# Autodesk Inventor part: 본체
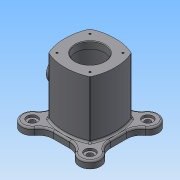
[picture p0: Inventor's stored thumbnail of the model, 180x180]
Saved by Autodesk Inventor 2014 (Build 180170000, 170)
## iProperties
Created: 2016-05
Part Number: 본체
Material: 일반
Document SubType Name: Modeling
Designer: NET
Density: 1 g/cm^3
Appearance: 기본값
Author: NET
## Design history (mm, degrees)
sketch "스케치5"
  geometry: L1 (0, 43)-(0, -43); L2 (-43, 0)-(43, 0); L3 (0, 0)-(35.355, 35.355); L4 (0, 0)-(-35.355, 35.355); L5 (0, 0)-(-35.355, -35.355); L6 (0, 0)-(35.355, -35.355); 4 further points; 4 other entities
  constraints: 12 end point, 2 coincident, 2 horizontal, 2 horizontal alignment, 2 midpoint, 2 vertical alignment, 18 other
  dimensions: "d44" = 50 distance of L3.end L3.start; "d46" = 50 distance of L4.end L3.start; "d47" = 50 distance of L5.end L3.start; "d48" = 45 deg angle of L2 L3; "d49" = 45 deg angle of L1 L4; "d50" = 45 deg angle of L1 L5; "d51" = 50 distance of L6.end L3.start; "d52" = 45 deg angle of L2 L6; "d53" = 86 distance of L1.end L1.start; "d54" = 86 distance of L2.start L2.end
extrude "돌출3" new body sketch "스케치5" distance "d55" = 110; taper "d56" = 0 deg
fillet "모깎기3" dims "d57" = 3
sketch "스케치6"
  geometry: L1 (110, -34.353)-(110, 34.353) reference; L2 (0, -34.353)-(0, 34.353) reference; L3 (110, 0)-(0, 0); L4 (110, -25)-(98, -25); L5 (98, -25)-(98, 0); L6 (98, -35)-(12, -35); L7 (12, -35)-(12, 0); L8 (0, -25)-(12, -25); L9 (12, -25)-(12, 0); L10 (98, -35)-(98, -25)
  constraints: 16 end point, 6 perpendicular, 5 point on line, 2 parallel, 1 midpoint
  dimensions: "d58" = 70 diameter of L6 L3; "d59" = 50 diameter of L4 L3; "d60" = 50 diameter of L8 L3; "d61" = 12 distance between parallel lines of L1 L5; "d62" = 12 distance between parallel lines of L2 L7
revolve "회전1" sketch "스케치6" stored, may be unused: angle "d63" = 90 deg
sketch "스케치7"
  geometry: L1 (-49, 49)-(49, 49); L2 (49, 49)-(49, -49); L3 (49, -49)-(-49, -49); L4 (-49, -49)-(-49, 49); L5 (0, 0)-(-49.497, -49.497); L6 (0, 0)-(0, -70); A1 r 18 centre (-49.497, -49.497) between (-34.706, -59.754) and (-59.754, -34.706); A2 r 25 centre (-14.162, -74) between (-14.162, -49) and (-34.706, -59.754); A3 r 25 centre (-74, -14.162) between (-59.754, -34.706) and (-49, -14.162); 3 further points
  constraints: 12 end point, 6 point on circle, 4 tangent, 3 centre point, 3 parallel, 2 coincident, 2 midpoint, 2 point on line, 1 horizontal, 1 horizontal alignment, 1 perpendicular, 1 vertical alignment
  dimensions: "d64" = 98 distance of L1.start L1.end; "d65" = 98 distance of L3.end L1.start; "d67" = 45 deg angle of L6 L5; "d68" = 18 radius of A1; "d69" = 25 radius of A2; "d70" = 25 radius of A3
extrude "돌출4" join sketch "스케치7" distance "d71" = 12; taper "d72" = 0 deg
sketch "스케치8" dims "d73" = 70
  geometry: L1 (49, -49)-(49, 14.162) reference; L2 (14.162, 49)-(-49, 49) reference; L3 (-49, 49)-(-49, -49) reference; L4 (-49, -49)-(49, -49) reference; L5 (0, 0)-(-49.497, 49.497); L6 (0, 0)-(0, 49); L7 (0, 0)-(-49.497, -49.497); L8 (0, 0)-(49.497, -49.497); C1 r 18 at (-49.497, 49.497); C2 r 18 at (-49.497, -49.497); C3 r 18 at (49.497, -49.497); A1 r 25 centre (-14.162, 74) between (-35.205, 60.503) and (-14.162, 49); A2 r 25 centre (-74, 14.162) between (-49, 14.162) and (-60.503, 35.205); A3 r 25 centre (-14.162, -74) between (-14.162, -49) and (-35.205, -60.503); A4 r 25 centre (-74, -14.162) between (-60.503, -35.205) and (-49, -14.162); A5 r 25 centre (14.162, -74) between (35.205, -60.503) and (14.162, -49); A6 r 25 centre (74, -14.162) between (49, -14.162) and (60.503, -35.205); 3 further points; 1 other entity
  constraints: 12 point on circle, 12 tangent, 9 centre point, 8 end point, 7 point on line, 4 coincident, 3 perpendicular, 12 other
  dimensions: "d75" = 45 deg angle of L6 L5; "d76" = 18 radius of C1; "d79" = 25 radius of A1; "d80" = 25 radius of A2; "d82" = 18 radius of C2; "d83" = 25 radius of A3; "d84" = 25 radius of A4; "d85" = 18 radius of C3; "d86" = 25 radius of A5; "d87" = 25 radius of A6
extrude "돌출5" join sketch "스케치8" distance "d88" = 10; taper "d89" = 0 deg
sketch "스케치9"
  geometry: L1 (49, -31.504)-(49, 14.162) reference; L2 (14.162, 49)-(-31.504, 49) reference; L3 (-49, 31.504)-(-49, -31.504) reference; L4 (-31.504, -49)-(31.504, -49) reference; A1 r 18 centre (-49.497, 49.497) between (-31.504, 49) and (-49, 31.504) reference; A2 r 18 centre (-49.497, -49.497) between (-49, -31.504) and (-31.504, -49) reference; A3 r 18 centre (49.497, -49.497) between (31.504, -49) and (49, -31.504) reference; A4 r 25 centre (-14.162, 74) between (-34.706, 59.754) and (-14.162, 49); A5 r 25 centre (-74, 14.162) between (-49, 14.162) and (-59.754, 34.706); A6 r 25 centre (-14.162, -74) between (-14.162, -49) and (-34.706, -59.754); A7 r 25 centre (14.162, -74) between (34.706, -59.754) and (14.162, -49); A8 r 25 centre (-74, -14.162) between (-59.754, -34.706) and (-49, -14.162); A9 r 25 centre (74, -14.162) between (49, -14.162) and (59.754, -34.706)
  constraints: 18 point on circle, 12 tangent, 6 centre point, 6 point on line
  dimensions: "d90" = 25 radius of A4; "d91" = 25 radius of A5; "d92" = 25 radius of A6; "d93" = 25 radius of A7; "d94" = 25 radius of A8; "d95" = 25 radius of A9
extrude "돌출6" join sketch "스케치9" distance "d96" = 12; taper "d97" = 0 deg
sketch "스케치10"
  geometry: C1 r 9 at (-49.497, 49.497); C2 r 9 at (49.497, 49.497); C3 r 9 at (49.497, -49.497); C4 r 9 at (-49.497, -49.497); A1 r 18 centre (49.497, 49.497) between (59.754, 34.706) and (34.706, 59.754) reference; A2 r 18 centre (-49.497, 49.497) between (-34.706, 59.754) and (-59.754, 34.706) reference; A3 r 18 centre (-49.497, -49.497) between (-59.754, -34.706) and (-34.706, -59.754) reference; A4 r 18 centre (49.497, -49.497) between (34.706, -59.754) and (59.754, -34.706) reference
  constraints: 4 centre point, 4 coincident
  dimensions: "d98" = 18 diameter of C1; "d99" = 18 diameter of C2; "d100" = 18 diameter of C3; "d101" = 18 diameter of C4
extrude "돌출7" cut sketch "스케치10" distance "d102" = 4; taper "d103" = 0 deg
sketch "스케치11"
  geometry: C1 r 9 at (0, 0) reference; C2 r 9 at (0, -98.995) reference; C3 r 9 at (98.995, -98.995) reference; C4 r 9 at (98.995, 0) reference; C5 r 5 at (0, -98.995); C6 r 5 at (98.995, -98.995); C7 r 5 at (98.995, 0); C8 r 5 at (0, 0); 1 further point
  constraints: 4 centre point, 4 coincident
  dimensions: "d104" = 10 diameter of C5; "d105" = 10 diameter of C6; "d106" = 10 diameter of C7; "d107" = 10 diameter of C8
extrude "돌출8" cut sketch "스케치11" stored distance "d108" = 4; taper "d109" = 0 deg
sketch "스케치12"
  geometry: L1 (0, 0)-(-28.284, 28.284); L2 (0, 0)-(0, 40); A1 r 40 centre (0, 0) between (-28.284, 28.284) and (0, 40); 3 further points; 1 other entity
  constraints: 4 end point, 2 point on circle, 1 centre point, 1 coincident, 1 vertical, 1 other
  dimensions: "d111" = 80 diameter of A1; "d112" = 45 deg angle of L2 L1
hole "구멍1" sketch "스케치12" at (-28.284, 28.284) diameter "d113" = 3.242; stored, may be unused: countersink angle "d117" = 90 deg, drill point angle "d119" = 118 deg; dims "d114" = 7, "d115" = 4, "d116" = 2, "d118" = 10
sketch "스케치13"
  geometry: C1 r 25 at (0, 0); 1 further point
  constraints: 1 centre point, 1 coincident
  dimensions: "d123" = 50 diameter of C1
extrude "돌출9" cut sketch "스케치13" distance "d124" = 50; taper "d125" = 0 deg
sketch "스케치14"
  geometry: L1 (-14.162, 49)-(14.162, 49) reference; L2 (0, 0)-(0, 40); L3 (0, 0)-(28.284, 28.284); C1 r 25 at (0, 0) reference; A1 r 40 centre (0, 0) between (0, 40) and (28.284, 28.284)
  constraints: 4 end point, 2 point on circle, 1 centre point, 1 coincident, 1 perpendicular
  dimensions: "d127" = 80 diameter of A1; "d128" = 45 deg angle of L2 L3
hole "구멍2" sketch "스케치14" at (28.284, 28.284) diameter "d129" = 3.242; stored, may be unused: countersink angle "d133" = 90 deg, drill point angle "d135" = 118 deg; dims "d130" = 7, "d131" = 4, "d132" = 2, "d134" = 10
node "작업 평면1"
sketch "스케치17"
  geometry: L1 (0, 0)-(49, 0); L2 (49, 0)-(61, 0); C1 r 20 at (61, 0)
  constraints: 4 end point, 1 centre point, 1 coincident, 1 collinear, 1 horizontal
  dimensions: "d146" = 49 distance of L1.start L1.end; "d147" = 12 distance of L1.end L2.end; "d148" = 40 diameter of C1
extrude "돌출11" join sketch "스케치17" stored distance "d149" = 50; taper "d150" = 10 deg
sketch "스케치19"
  geometry: C1 r 20 at (0, 0) reference; C2 r 15 at (0, 0); 1 further point
  constraints: 1 centre point, 1 coincident
  dimensions: "d151" = 30 diameter of C2
extrude "돌출12" cut sketch "스케치19" distance "d152" = 8; taper "d153" = 0 deg
sketch "스케치20"
  geometry: C1 r 15 at (0, 0) reference; C2 r 12.5 at (0, 0); 1 further point
  constraints: 1 centre point, 1 coincident
  dimensions: "d154" = 25 diameter of C2
extrude "돌출13" cut sketch "스케치20" distance "d155" = 33; taper "d156" = 0 deg
node "작업 평면2"
sketch "스케치21"
  geometry: L1 (12, 34.353)-(12, -34.353) reference; L2 (110, -34.353)-(12, -34.353) reference; L3 (110, 34.353)-(110, -34.353) reference; L4 (12, 34.353)-(110, 34.353) reference; L5 (12, 35.826)-(12, 35.826) reference; L6 (110, 35.826)-(12, 35.826) reference; L7 (110, 35.826)-(110, 35.826) reference; L8 (12, 35.826)-(110, 35.826) reference; L9 (110, 35.826)-(110, 43) reference; 3 further points
  constraints: 2 other
  dimensions: "d158" = 29 vertical distance of point (0, 0) point (61, 29); "d159" = 49 distance from line of L3 point (61, 29)
  node "투영된 루프3"
  node "투영된 루프4"
extrude "돌출14" join sketch "스케치21" distance "d162" = 0.5; taper "d163" = 0 deg
extrude "돌출15" join sketch "스케치21" distance "d164" = 0.5; taper "d165" = 0 deg
fillet "모깎기4" dims "d166" = 3
chamfer "모따기1" distance "d167" = 1; stored, may be unused: second distance "d168" = 2, angle "d169" = 45 deg
chamfer "모따기2" distance "d170" = 1; stored, may be unused: second distance "d171" = 2, angle "d172" = 45 deg
fillet "모깎기5" dims "d173" = 3
sketch "스케치23"
  geometry: L1 (-31.504, 49)-(-44.522, 49) reference; L2 (-49, 44.522)-(-49, 31.504) reference; L3 (49, 31.504)-(49, 44.522) reference; L4 (44.522, 49)-(31.504, 49) reference; A1 r 5 centre (-49.497, 49.497) between (-44.522, 49) and (-49, 44.522) reference; A2 r 18 centre (-49.497, 49.497) between (-31.504, 49) and (-34.706, 59.754) reference; A3 r 18 centre (-49.497, 49.497) between (-34.706, 59.754) and (-59.754, 34.706) reference; A4 r 18 centre (-49.497, 49.497) between (-59.754, 34.706) and (-49, 31.504) reference; A5 r 5 centre (49.497, 49.497) between (49, 44.522) and (44.522, 49) reference; A6 r 18 centre (49.497, 49.497) between (49, 31.504) and (59.754, 34.706) reference; A7 r 18 centre (49.497, 49.497) between (59.754, 34.706) and (34.706, 59.754) reference; A8 r 18 centre (49.497, 49.497) between (34.706, 59.754) and (31.504, 49) reference; 1 further point
extrude "돌출16" join sketch "스케치23" distance "d174" = 2; taper "d175" = 0 deg
sketch "스케치24"
  geometry: L1 (-49, -31.504)-(-49, -44.522) reference; L2 (-44.522, -49)-(-31.504, -49) reference; A1 r 5 centre (-49.497, -49.497) between (-49, -44.522) and (-44.522, -49) reference; A2 r 18 centre (-49.497, -49.497) between (-49, -31.504) and (-59.754, -34.706) reference; A3 r 18 centre (-49.497, -49.497) between (-59.754, -34.706) and (-34.706, -59.754) reference; A4 r 18 centre (-49.497, -49.497) between (-34.706, -59.754) and (-31.504, -49) reference; 1 further point
extrude "돌출17" join sketch "스케치24" distance "d176" = 2; taper "d177" = 0 deg
node "솔리드3"
pattern_circular "원형 패턴1" dims angle "d121" = 360 deg
pattern_circular "원형 패턴2" dims angle "d137" = 360 deg
node "투영된 루프1"
node "투영된 루프2"
node "투영된 루프5"
other parameters: "d139" = 55, "d157" = 43
